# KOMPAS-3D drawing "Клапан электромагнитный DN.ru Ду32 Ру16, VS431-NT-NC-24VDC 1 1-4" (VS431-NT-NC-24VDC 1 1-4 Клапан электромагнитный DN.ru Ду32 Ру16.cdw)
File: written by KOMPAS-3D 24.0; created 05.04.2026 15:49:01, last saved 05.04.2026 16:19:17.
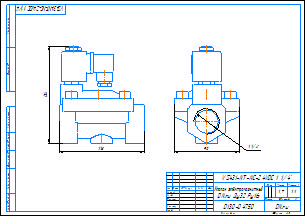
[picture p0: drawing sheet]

Document properties: c3d_UniqueCompID: ef56311e-7521-43dc-8291-0e6108b3d81d; Автор: artio; Класс точности: c; Знак неуказанной шероховатости: Шероховатость не задана; Рассекать на разрезах: Да; c3d_UniqueCompID: ef56311e-7521-43dc-8291-0e6108b3d81d; Автор: artio; Класс точности: c; Знак неуказанной шероховатости: Шероховатость не задана; Рассекать на разрезах: Да; c3d_UniqueCompID: ef56311e-7521-43dc-8291-0e6108b3d81d; Автор: artio; Класс точности: c; Знак неуказанной шероховатости: Шероховатость не задана; Рассекать на разрезах: Да; Автор: artio; Форматы листов документа: A3; Полное имя файла: VS431-NT-NC-24VDC 1 1-4 Клапан электромагнитный DN.ru Ду32 Ру16.m3d; Масса: 1.701; Наименование: Клапан электромагнитный DN.ru Ду32 Ру16; Количество листов документа: 1; Примечание: D130-04750

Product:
- Body: Тело 1  | qty 1
    Масса: 3.709873
- Part/product: Клапан электромагнитный DN.ru Ду32 Ру16  | designation VS431-NT-NC-24VDC 1 1-4
    Масса: 1.701
    Раздел спецификации: Прочие изделия
    Примечание: D130-04750
    additional columns: ef56311e-7521-43dc-8291-0e6108b3d81d; artio; c; Шероховатость не задана; Да

Views: Вид 1, Спереди
Referenced files in C:\Users\artio\OneDrive\Рабочий стол\Клапан электромагнитный DN.ru\VS431\VS431-ET-NC\: VS431-ET-NC-24VDC 3-4 Клапан электромагнитный DN.ru Ду20 Ру16.m3d, VS431-ET-NC-24VDC 3-4 Клапан электромагнитный DN.ru Ду20 Ру16.cdw
Referenced files in C:\Users\artio\OneDrive\Рабочий стол\Клапан электромагнитный DN.ru\VS431\VS431-NT-NC\: VS431-NT-NC-24VDC 1 1-4 Клапан электромагнитный DN.ru Ду32 Ру16.m3d
Referenced files in C:\Users\artio\OneDrive\Рабочий стол\Клапан электромагнитный DN.ru\VS431\VS431-NT-NC\VS431-NT-NC-24VDC\Ду32\: VS431-NT-NC-24VDC 1 1-4 Клапан электромагнитный DN.ru Ду32 Ру16.m3d
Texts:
  VS431-NT-NC-24VDC 1 1-4
  Клапан электромагнитный
  DN.ru Ду32 Ру16
  VS431-NT-NC-24VDC 1 1/4"
  VS431-NT-NC-24VDC 1 1/4"-
  Клапан электромагнитный DN.ru Ду32 Ру16
  VS431-NT-NC-24VDC 1 1-4 Клапан электромагнитный DN.ru Ду32 Ру16
Dimensions and other numbers on the sheet: 0; 3; 2; 4; 90; 1 1/4"; 1:1; 1; 1,7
